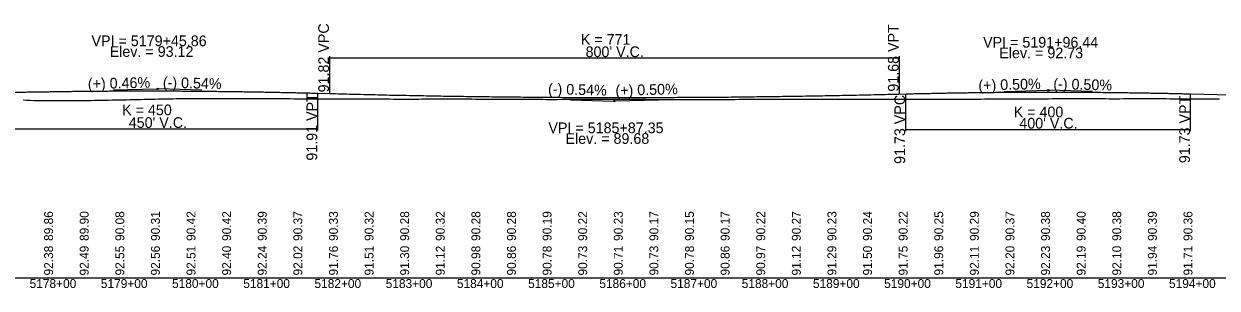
# Model space of a CAD drawing. Extents: x 2121671 to 2169879, y 557274 to 599957.
# Drawn here: x 2147326 to 2149002, y 598693 to 599064 of the extents above; entities that cross this region are included whole.
import ezdxf

# ---------------------------------------------------------------- set-up
doc = ezdxf.new("R2010")
doc.units = 0
for name, color, linetype in [('RD_DDB_GradeTX', 7, 'Continuous'), ('RD_DDB_Profile_EX', 7, 'Continuous'), ('RD_DDB_Profile_Lbl', 7, 'Continuous'), ('RD_DDB_Profile_PR', 7, 'Continuous'), ('RD_DDB_StaTX', 7, 'Continuous'), ('RD_DDB_StripGrade', 7, 'Continuous'), ('RD_DDB_VCLbl', 7, 'Continuous'), ('RD_GPK_Profile_Cell', 7, 'Continuous')]:
    doc.layers.add(name, color=color, linetype=linetype)

msp = doc.modelspace()

# ---------------------------------------------------------------- linework, layer by layer
at = {"layer": 'RD_DDB_GradeTX'}
for p, q in [((2147452.1, 598971.6), (2147513.1, 598973)), ((2147576.1, 598971.4), (2147515.1, 598973)), ((2148702.7, 598969.6), (2148763.7, 598971.1)), ((2148826.7, 598969.6), (2148765.7, 598971.1)), ((2148093.6, 598957.5), (2148154.6, 598955.9)), ((2148217.6, 598957.4), (2148156.6, 598955.9))]:
    msp.add_line(p, q, dxfattribs=at)
for centre in [(2147514.1, 598973.1), (2148764.7, 598971.1), (2148155.6, 598955.9)]:
    msp.add_circle(centre, 1, dxfattribs=at)
at = {"layer": 'RD_DDB_Profile_EX'}
for points in [[(2147325.2, 598957.6), (2147330.2, 598957.4), (2147335.2, 598957.2), (2147340.2, 598957), (2147345.2, 598956.9), (2147350.2, 598956.9), (2147355.2, 598956.9), (2147360.2, 598956.8), (2147365.2, 598956.8), (2147370.2, 598956.7), (2147375.2, 598956.7), (2147380.2, 598956.7), (2147385.2, 598956.7), (2147390.2, 598956.7), (2147395.2, 598956.7), (2147400.2, 598956.8), (2147405.2, 598956.8), (2147410.2, 598956.9), (2147415.2, 598957), (2147420.2, 598957), (2147425.2, 598957.1), (2147430.2, 598957.2), (2147435.2, 598957.3), (2147440.2, 598957.3), (2147445.2, 598957.4), (2147450.2, 598957.5), (2147455.2, 598957.6), (2147460.2, 598957.7), (2147465.2, 598957.8), (2147470.2, 598957.9), (2147475.2, 598958), (2147480.2, 598958.2), (2147485.2, 598958.3), (2147490.2, 598958.4), (2147495.2, 598958.5), (2147500.2, 598958.7), (2147505.2, 598958.8), (2147510.2, 598958.9), (2147515.2, 598959), (2147520.2, 598959.1), (2147525.2, 598959.2), (2147530.2, 598959.2), (2147535.2, 598959.3), (2147540.2, 598959.4), (2147545.2, 598959.5), (2147550.2, 598959.5), (2147555.2, 598959.5), (2147560.2, 598959.5), (2147565.2, 598959.5), (2147570.2, 598959.6), (2147575.2, 598959.6), (2147580.2, 598959.6), (2147585.2, 598959.6), (2147590.2, 598959.6), (2147595.2, 598959.6), (2147600.2, 598959.6), (2147605.2, 598959.6), (2147610.2, 598959.6), (2147615.2, 598959.6), (2147620.2, 598959.6), (2147625.2, 598959.5), (2147630.2, 598959.5), (2147635.2, 598959.5), (2147640.2, 598959.5), (2147645.2, 598959.5), (2147650.2, 598959.5), (2147655.2, 598959.5), (2147660.2, 598959.4), (2147665.2, 598959.4), (2147670.2, 598959.4), (2147675.2, 598959.4), (2147680.2, 598959.4), (2147685.2, 598959.4), (2147690.2, 598959.4), (2147695.2, 598959.4), (2147700.2, 598959.4), (2147705.2, 598959.3), (2147710.2, 598959.3), (2147715.2, 598959.3)], [(2147715.2, 598959.3), (2147720.2, 598959.3), (2147725.2, 598959.3), (2147730.2, 598959.3), (2147735.2, 598959.2), (2147740.2, 598959.2), (2147745.2, 598959.2), (2147750.2, 598959.2), (2147755.2, 598959.2), (2147760.2, 598959.2), (2147765.2, 598959.1), (2147770.2, 598959.1), (2147775.2, 598959.1), (2147780.2, 598959.1), (2147785.2, 598959.1), (2147790.2, 598959.1), (2147795.2, 598959.1), (2147800.2, 598959.1), (2147805.2, 598959.1), (2147810.2, 598959.1), (2147815.2, 598959), (2147820.2, 598959), (2147825.2, 598959), (2147830.2, 598959), (2147835.2, 598959), (2147840.2, 598959), (2147845.2, 598958.9), (2147850.2, 598958.9), (2147855.2, 598958.9), (2147860.2, 598958.9), (2147865.2, 598958.9), (2147870.2, 598958.9), (2147875.2, 598958.9), (2147880.2, 598958.9), (2147885.2, 598959), (2147890.2, 598959), (2147895.2, 598959), (2147900.2, 598959.1), (2147905.2, 598959.1), (2147910.2, 598959.1), (2147915.2, 598959.1), (2147920.2, 598959.1), (2147925.2, 598959.1), (2147930.2, 598959), (2147935.2, 598959), (2147940.2, 598959), (2147945.2, 598959), (2147950.2, 598959), (2147955.2, 598959), (2147960.2, 598958.9), (2147965.2, 598958.9), (2147970.2, 598958.9), (2147975.2, 598958.9), (2147980.2, 598958.8), (2147985.2, 598958.8), (2147990.2, 598958.8), (2147995.2, 598958.8), (2148000.2, 598958.8), (2148005.2, 598958.8), (2148010.2, 598958.8), (2148015.2, 598958.8), (2148020.2, 598958.9), (2148025.2, 598958.8), (2148030.2, 598958.8), (2148035.2, 598958.7), (2148040.2, 598958.7), (2148045.2, 598958.6), (2148050.2, 598958.6), (2148055.2, 598958.5), (2148060.2, 598958.4), (2148065.2, 598958.4), (2148070.2, 598958.4), (2148075.2, 598958.4), (2148080.2, 598958.5), (2148085.2, 598958.5), (2148090.2, 598958.5), (2148095.2, 598958.5), (2148100.2, 598958.5), (2148105.2, 598958.5), (2148110.2, 598958.5), (2148115.2, 598958.5), (2148120.2, 598958.6), (2148125.2, 598958.6), (2148130.2, 598958.6), (2148135.2, 598958.6), (2148140.2, 598958.6), (2148145.2, 598958.6), (2148150.2, 598958.6), (2148155.2, 598958.6), (2148160.2, 598958.6), (2148165.2, 598958.6), (2148170.2, 598958.6), (2148175.2, 598958.6), (2148180.2, 598958.6), (2148185.2, 598958.6), (2148190.2, 598958.6), (2148195.2, 598958.5), (2148200.2, 598958.5), (2148205.2, 598958.4), (2148210.2, 598958.4), (2148215.2, 598958.3)], [(2148215.2, 598958.3), (2148220.2, 598958.3), (2148225.2, 598958.3), (2148230.2, 598958.3), (2148235.2, 598958.3), (2148240.2, 598958.3), (2148245.2, 598958.3), (2148250.2, 598958.3), (2148255.2, 598958.3), (2148260.2, 598958.3), (2148265.2, 598958.2), (2148270.2, 598958.2), (2148275.2, 598958.2), (2148280.2, 598958.2), (2148285.2, 598958.2), (2148290.2, 598958.2), (2148295.2, 598958.1), (2148300.2, 598958.1), (2148305.2, 598958.2), (2148310.2, 598958.2), (2148315.2, 598958.3), (2148320.2, 598958.4), (2148325.2, 598958.4), (2148330.2, 598958.5), (2148335.2, 598958.6), (2148340.2, 598958.6), (2148345.2, 598958.6), (2148350.2, 598958.6), (2148355.2, 598958.6), (2148360.2, 598958.6), (2148365.2, 598958.6), (2148370.2, 598958.5), (2148375.2, 598958.5), (2148380.2, 598958.5), (2148385.2, 598958.5), (2148390.2, 598958.6), (2148395.2, 598958.6), (2148400.2, 598958.7), (2148405.2, 598958.7), (2148410.2, 598958.8), (2148415.2, 598958.8), (2148420.2, 598958.8), (2148425.2, 598958.8), (2148430.2, 598958.8), (2148435.2, 598958.8), (2148440.2, 598958.7), (2148445.2, 598958.7), (2148450.2, 598958.7), (2148455.2, 598958.6), (2148460.2, 598958.6), (2148465.2, 598958.6), (2148470.2, 598958.6), (2148475.2, 598958.6), (2148480.2, 598958.7), (2148485.2, 598958.7), (2148490.2, 598958.7), (2148495.2, 598958.7), (2148500.2, 598958.7), (2148505.2, 598958.7), (2148510.2, 598958.7), (2148515.2, 598958.7), (2148520.2, 598958.6), (2148525.2, 598958.6), (2148530.2, 598958.6), (2148535.2, 598958.6), (2148540.2, 598958.6), (2148545.2, 598958.6), (2148550.2, 598958.6), (2148555.2, 598958.6), (2148560.2, 598958.6), (2148565.2, 598958.6), (2148570.2, 598958.6), (2148575.2, 598958.6), (2148580.2, 598958.6), (2148585.2, 598958.6), (2148590.2, 598958.6), (2148595.2, 598958.6), (2148600.2, 598958.7), (2148605.2, 598958.7), (2148610.2, 598958.7), (2148615.2, 598958.7), (2148620.2, 598958.7), (2148625.2, 598958.7), (2148630.2, 598958.7), (2148635.2, 598958.7), (2148640.2, 598958.8), (2148645.2, 598958.8), (2148650.2, 598958.8), (2148655.2, 598958.8), (2148660.2, 598958.8), (2148665.2, 598958.9), (2148670.2, 598958.9), (2148675.2, 598959), (2148680.2, 598959.1), (2148685.2, 598959.1), (2148690.2, 598959.2), (2148695.2, 598959.3), (2148700.2, 598959.3), (2148705.2, 598959.3), (2148710.2, 598959.3), (2148715.2, 598959.3)], [(2148715.2, 598959.3), (2148720.2, 598959.3), (2148725.2, 598959.3), (2148730.2, 598959.3), (2148735.2, 598959.3), (2148740.2, 598959.2), (2148745.2, 598959.3), (2148750.2, 598959.3), (2148755.2, 598959.3), (2148760.2, 598959.3), (2148765.2, 598959.3), (2148770.2, 598959.4), (2148775.2, 598959.4), (2148780.2, 598959.4), (2148785.2, 598959.4), (2148790.2, 598959.4), (2148795.2, 598959.4), (2148800.2, 598959.4), (2148805.2, 598959.4), (2148810.2, 598959.5), (2148815.2, 598959.5), (2148820.2, 598959.5), (2148825.2, 598959.5), (2148830.2, 598959.4), (2148835.2, 598959.4), (2148840.2, 598959.4), (2148845.2, 598959.4), (2148850.2, 598959.3), (2148855.2, 598959.3), (2148860.2, 598959.3), (2148865.2, 598959.3), (2148870.2, 598959.4), (2148875.2, 598959.4), (2148880.2, 598959.4), (2148885.2, 598959.5), (2148890.2, 598959.5), (2148895.2, 598959.5), (2148900.2, 598959.5), (2148905.2, 598959.5), (2148910.2, 598959.5), (2148915.2, 598959.4), (2148920.2, 598959.4), (2148925.2, 598959.4), (2148930.2, 598959.4), (2148935.2, 598959.3), (2148940.2, 598959.3), (2148945.2, 598959.3), (2148950.2, 598959.3), (2148955.2, 598959.3), (2148960.2, 598959.3), (2148965.2, 598959.3), (2148970.2, 598959.3), (2148975.2, 598959.3), (2148980.2, 598959.3), (2148985.2, 598959.3), (2148990.2, 598959.3), (2148995.2, 598959.3), (2149000.2, 598959.2), (2149005.2, 598959.2)]]:
    msp.add_lwpolyline(points, dxfattribs=at)
at = {"layer": 'RD_DDB_Profile_PR'}
for p, q in [((2147739.1, 598967), (2147755.6, 598966.6)), ((2148555.6, 598965.9), (2148564.7, 598966.1)), ((2148964.7, 598966.1), (2149161.5, 598961.2))]:
    msp.add_line(p, q, dxfattribs=at)
for points in [[(2147289.1, 598967.9), (2147298.1, 598968.1), (2147307.1, 598968.3), (2147316.1, 598968.4), (2147325.1, 598968.6), (2147334.1, 598968.8), (2147343.1, 598968.9), (2147352.1, 598969.1), (2147361.1, 598969.2), (2147370.1, 598969.4), (2147379.1, 598969.5), (2147388.1, 598969.6), (2147397.1, 598969.7), (2147406.1, 598969.8), (2147415.1, 598969.9), (2147424.1, 598970), (2147433.1, 598970), (2147442.1, 598970.1), (2147451.1, 598970.2), (2147460.1, 598970.2), (2147469.1, 598970.2), (2147478.1, 598970.3), (2147487.1, 598970.3), (2147496.1, 598970.3), (2147505.1, 598970.3), (2147514.1, 598970.3), (2147523.1, 598970.2), (2147532.1, 598970.2), (2147541.1, 598970.2), (2147550.1, 598970.1), (2147559.1, 598970.1), (2147568.1, 598970), (2147577.1, 598969.9), (2147586.1, 598969.8), (2147595.1, 598969.7), (2147604.1, 598969.6), (2147613.1, 598969.5), (2147622.1, 598969.4), (2147631.1, 598969.3), (2147640.1, 598969.1), (2147649.1, 598969), (2147658.1, 598968.8), (2147667.1, 598968.7), (2147676.1, 598968.5), (2147685.1, 598968.3), (2147694.1, 598968.1), (2147703.1, 598967.9), (2147712.1, 598967.7), (2147721.1, 598967.5), (2147730.1, 598967.3), (2147739.1, 598967)], [(2147755.6, 598966.6), (2147771.6, 598966.2), (2147787.6, 598965.8), (2147803.6, 598965.4), (2147819.6, 598965), (2147835.6, 598964.6), (2147851.6, 598964.3), (2147867.6, 598964), (2147883.6, 598963.7), (2147899.6, 598963.4), (2147915.6, 598963.1), (2147931.6, 598962.9), (2147947.6, 598962.6), (2147963.6, 598962.4), (2147979.6, 598962.2), (2147995.6, 598962), (2148011.6, 598961.8), (2148027.6, 598961.7), (2148043.6, 598961.6), (2148059.6, 598961.4), (2148075.6, 598961.3), (2148091.6, 598961.2), (2148107.6, 598961.2), (2148123.6, 598961.1), (2148139.6, 598961.1), (2148155.6, 598961), (2148171.6, 598961), (2148187.6, 598961), (2148203.6, 598961.1), (2148219.6, 598961.1), (2148235.6, 598961.2), (2148251.6, 598961.3), (2148267.6, 598961.4), (2148283.6, 598961.5), (2148299.6, 598961.6), (2148315.6, 598961.7), (2148331.6, 598961.9), (2148347.6, 598962.1), (2148363.6, 598962.3), (2148379.6, 598962.5), (2148395.6, 598962.7), (2148411.6, 598962.9), (2148427.6, 598963.2), (2148443.6, 598963.5), (2148459.6, 598963.8), (2148475.6, 598964.1), (2148491.6, 598964.4), (2148507.6, 598964.8), (2148523.6, 598965.1), (2148539.6, 598965.5), (2148555.6, 598965.9)], [(2148564.7, 598966.1), (2148572.7, 598966.3), (2148580.7, 598966.5), (2148588.7, 598966.7), (2148596.7, 598966.8), (2148604.7, 598967), (2148612.7, 598967.2), (2148620.7, 598967.3), (2148628.7, 598967.5), (2148636.7, 598967.6), (2148644.7, 598967.7), (2148652.7, 598967.8), (2148660.7, 598967.9), (2148668.7, 598968), (2148676.7, 598968.1), (2148684.7, 598968.2), (2148692.7, 598968.3), (2148700.7, 598968.4), (2148708.7, 598968.4), (2148716.7, 598968.5), (2148724.7, 598968.5), (2148732.7, 598968.6), (2148740.7, 598968.6), (2148748.7, 598968.6), (2148756.7, 598968.6), (2148764.7, 598968.6), (2148772.7, 598968.6), (2148780.7, 598968.6), (2148788.7, 598968.6), (2148796.7, 598968.6), (2148804.7, 598968.5), (2148812.7, 598968.5), (2148820.7, 598968.4), (2148828.7, 598968.4), (2148836.7, 598968.3), (2148844.7, 598968.2), (2148852.7, 598968.1), (2148860.7, 598968), (2148868.7, 598967.9), (2148876.7, 598967.8), (2148884.7, 598967.7), (2148892.7, 598967.6), (2148900.7, 598967.5), (2148908.7, 598967.3), (2148916.7, 598967.2), (2148924.7, 598967), (2148932.7, 598966.9), (2148940.7, 598966.7), (2148948.7, 598966.5), (2148956.7, 598966.3), (2148964.7, 598966.1)]]:
    msp.add_spline(points, degree=3, dxfattribs=at)
at = {"layer": 'RD_DDB_VCLbl'}
for p, q in [((2147755.6, 599019.1), (2147755.6, 598966.6)), ((2147755.6, 599016.6), (2148555.6, 599016.6)), ((2148555.6, 599019.1), (2148555.6, 598965.9)), ((2147739.1, 598914.5), (2147739.1, 598967)), ((2148564.7, 598913.6), (2148564.7, 598966.1)), ((2148964.7, 598913.6), (2148964.7, 598966.1)), ((2147289.1, 598917), (2147739.1, 598917)), ((2148564.7, 598916.1), (2148964.7, 598916.1))]:
    msp.add_line(p, q, dxfattribs=at)
at = {"layer": 'RD_GPK_Profile_Cell'}
msp.add_line((2146668.2, 598707.5), (2151268.2, 598707.5), dxfattribs=at)
msp.add_line((2146668.2, 598707.5), (2151268.2, 598707.5), dxfattribs=at)
msp.add_line((2146668.2, 598707.5), (2151268.2, 598707.5), dxfattribs=at)

# ---------------------------------------------------------------- texts
at = {"layer": 'RD_DDB_GradeTX'}
for s, rotation, p in [('(+) 0.46%', 1.3258, (2147416.2, 598972.8)), ('(-) 0.54%', 358.4628, (2147521.2, 598974.9)), ('(+) 0.50%', 1.4356, (2148666.8, 598970.7)), ('(-) 0.50%', 358.5698, (2148771.7, 598972.9)), ('(-) 0.54%', 358.4628, (2148062.1, 598965.8)), ('(+) 0.50%', 1.4356, (2148157.1, 598963.4))]:
    msp.add_text(s, height=15, rotation=rotation, dxfattribs=at).set_placement(p)
at = {"layer": 'RD_DDB_Profile_Lbl'}
for s, p in [('VPI = 5179+45.86', (2147421.2, 599033.1)), ('VPI = 5191+96.44', (2148673.2, 599031.1)), ('Elev. = 93.12', (2147446.7, 599018.1)), ('Elev. = 92.73', (2148696, 599016.1)), ('VPI = 5185+87.35', (2148062.8, 598910.9)), ('Elev. = 89.68', (2148086.8, 598895.9))]:
    msp.add_text(s, height=15, dxfattribs=at).set_placement(p)
at = {"layer": 'RD_DDB_StaTX'}
for s, p in [('5178+00', (2147334.3, 598693.4)), ('5179+00', (2147434.3, 598693.4)), ('5180+00', (2147534.3, 598693.4)), ('5181+00', (2147634.3, 598693.4)), ('5182+00', (2147734.3, 598693.4)), ('5183+00', (2147834.3, 598693.4)), ('5184+00', (2147934.3, 598693.4)), ('5185+00', (2148034.3, 598693.4)), ('5186+00', (2148134.3, 598693.4)), ('5187+00', (2148234.3, 598693.4)), ('5188+00', (2148334.3, 598693.4)), ('5189+00', (2148434.3, 598693.4)), ('5190+00', (2148534.3, 598693.4)), ('5191+00', (2148634.3, 598693.4)), ('5192+00', (2148734.3, 598693.4)), ('5193+00', (2148834.3, 598693.4)), ('5194+00', (2148934.3, 598693.4))]:
    msp.add_text(s, height=12.5, dxfattribs=at).set_placement(p)
at = {"layer": 'RD_DDB_StripGrade'}
for s, height, p in [('91.82 VPC', 15, (2147754.6, 598968.2)), ('91.68 VPT', 15, (2148554.6, 598969.2)), ('91.91 VPT', 15, (2147738.1, 598872.3)), ('91.73 VPC', 15, (2148563.7, 598867.7)), ('91.73 VPT', 15, (2148963.7, 598868.7)), ('89.86', 12.5, (2147367.2, 598759.5)), ('89.90', 12.5, (2147417.2, 598759.5)), ('90.08', 12.5, (2147467.2, 598759.5)), ('90.31', 12.5, (2147517.2, 598759.5)), ('90.42', 12.5, (2147567.2, 598759.5)), ('90.42', 12.5, (2147617.2, 598759.5)), ('90.39', 12.5, (2147667.2, 598759.5)), ('90.37', 12.5, (2147717.2, 598759.5)), ('90.33', 12.5, (2147767.2, 598759.5)), ('90.32', 12.5, (2147817.2, 598759.5)), ('90.28', 12.5, (2147867.2, 598759.5)), ('90.32', 12.5, (2147917.2, 598759.5)), ('90.28', 12.5, (2147967.2, 598759.5)), ('90.28', 12.5, (2148017.2, 598759.5)), ('90.19', 12.5, (2148067.2, 598759.5)), ('90.22', 12.5, (2148117.2, 598759.5)), ('90.23', 12.5, (2148167.2, 598759.5)), ('90.17', 12.5, (2148217.2, 598759.5)), ('90.15', 12.5, (2148267.2, 598759.5)), ('90.17', 12.5, (2148317.2, 598759.5)), ('90.22', 12.5, (2148367.2, 598759.5)), ('90.27', 12.5, (2148417.2, 598759.5)), ('90.23', 12.5, (2148467.2, 598759.5)), ('90.24', 12.5, (2148517.2, 598759.5)), ('90.22', 12.5, (2148567.2, 598759.5)), ('90.25', 12.5, (2148617.2, 598759.5)), ('90.29', 12.5, (2148667.2, 598759.5)), ('90.37', 12.5, (2148717.2, 598759.5)), ('90.38', 12.5, (2148767.2, 598759.5)), ('90.40', 12.5, (2148817.2, 598759.5)), ('90.38', 12.5, (2148867.2, 598759.5)), ('90.39', 12.5, (2148917.2, 598759.5)), ('90.36', 12.5, (2148967.2, 598759.5)), ('92.38', 12.5, (2147367.2, 598711)), ('92.49', 12.5, (2147417.2, 598711)), ('92.55', 12.5, (2147467.2, 598711)), ('92.56', 12.5, (2147517.2, 598711)), ('92.51', 12.5, (2147567.2, 598711)), ('92.40', 12.5, (2147617.2, 598711)), ('92.24', 12.5, (2147667.2, 598711)), ('92.02', 12.5, (2147717.2, 598711)), ('91.76', 12.5, (2147767.2, 598711)), ('91.51', 12.5, (2147817.2, 598711)), ('91.30', 12.5, (2147867.2, 598711)), ('91.12', 12.5, (2147917.2, 598711)), ('90.98', 12.5, (2147967.2, 598711)), ('90.86', 12.5, (2148017.2, 598711)), ('90.78', 12.5, (2148067.2, 598711)), ('90.73', 12.5, (2148117.2, 598711)), ('90.71', 12.5, (2148167.2, 598711)), ('90.73', 12.5, (2148217.2, 598711)), ('90.78', 12.5, (2148267.2, 598711)), ('90.86', 12.5, (2148317.2, 598711)), ('90.97', 12.5, (2148367.2, 598711)), ('91.12', 12.5, (2148417.2, 598711)), ('91.29', 12.5, (2148467.2, 598711)), ('91.50', 12.5, (2148517.2, 598711)), ('91.75', 12.5, (2148567.2, 598711)), ('91.96', 12.5, (2148617.2, 598711)), ('92.11', 12.5, (2148667.2, 598711)), ('92.20', 12.5, (2148717.2, 598711)), ('92.23', 12.5, (2148767.2, 598711)), ('92.19', 12.5, (2148817.2, 598711)), ('92.10', 12.5, (2148867.2, 598711)), ('91.94', 12.5, (2148917.2, 598711)), ('91.71', 12.5, (2148967.2, 598711))]:
    msp.add_text(s, height=height, rotation=90, dxfattribs=at).set_placement(p)
at = {"layer": 'RD_DDB_VCLbl'}
for s, p in [('K = 771', (2148108.3, 599035.1)), ("800' V.C.", (2148115, 599017.8)), ('K = 450', (2147464.2, 598936.1)), ('K = 400', (2148716.2, 598933.2)), ("450' V.C.", (2147473.5, 598918.3)), ("400' V.C.", (2148724.1, 598917.4))]:
    msp.add_text(s, height=15, dxfattribs=at).set_placement(p)

doc.saveas('drawing.dxf')
